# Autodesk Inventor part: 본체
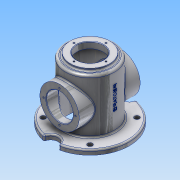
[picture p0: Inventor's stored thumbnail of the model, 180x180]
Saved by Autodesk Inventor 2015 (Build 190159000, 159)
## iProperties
Created: 2018-04
Part Number: 본체
Material: 알루미늄 6061
Document SubType Name: Modeling
Designer: SCD-A04
Density: 2.7 g/cm^3
Appearance: 알루미늄 - 평지
Mass: 1147.05 g
Surface Area: 1200.36 cm^2
Volume: 424.833 cm^3
Author: SCD-A04
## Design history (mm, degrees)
sketch "스케치1"
  geometry: C1 r 80 at (0, 0); 1 further point
  constraints: 1 centre point, 1 coincident
  dimensions: "d0" = 160 diameter of C1
extrude "돌출1" new body sketch "스케치1" distance "d1" = 10; taper "d2" = 0 deg
sketch "스케치2"
  geometry: C1 r 80 at (0, 0) reference; C2 r 50 at (0, 0)
  constraints: 1 centre point, 1 coincident
  dimensions: "d3" = 100 diameter of C2
extrude "돌출2" join sketch "스케치2" distance "d4" = 8; taper "d5" = 0 deg
sketch "스케치3"
  geometry: C1 r 80 at (0, 0) reference; C2 r 50 at (0, 0)
  constraints: 1 centre point, 1 coincident
  dimensions: "d6" = 100 diameter of C2
extrude "돌출3" join sketch "스케치3" distance "d7" = 110; taper "d8" = 0 deg
sketch "스케치4"
  geometry: C1 r 50 at (0, 0) reference; C2 r 40 at (0, 0)
  constraints: 1 centre point, 1 coincident
  dimensions: "d9" = 80 diameter of C2
extrude "돌출4" join sketch "스케치4" distance "d10" = 5; taper "d11" = 0 deg
node "작업 평면1"
sketch "스케치5"
  geometry: L1 (-80, 0)-(80, 0) reference; C1 r 40 at (0, 60); 1 further point
  constraints: 1 centre point, 1 vertical alignment
  dimensions: "d13" = 80 diameter of C1; "d14" = 60 distance from line of L1 C1.centre
extrude "돌출5" join sketch "스케치5" distance "d15" = 124; taper "d16" = 0 deg
hole "구멍1" diameter "d19" = 90; stored, may be unused: countersink angle "d23" = 90 deg, drill point angle "d25" = 0 deg; dims "d17" = 10, "d18" = 10, "d20" = 6, "d21" = 4, "d22" = 2, "d24" = 120
hole "구멍2" diameter "d28" = 54; stored, may be unused: countersink angle "d32" = 90 deg, drill point angle "d34" = 0 deg; dims "d26" = 10, "d27" = 10, "d29" = 6, "d30" = 4, "d31" = 2, "d33" = 120
hole "구멍3" diameter "d37" = 54; stored, may be unused: countersink angle "d41" = 90 deg, drill point angle "d43" = 0 deg; dims "d35" = 10, "d36" = 10, "d38" = 6, "d39" = 4, "d40" = 2, "d42" = 120
sketch "스케치6"
  geometry: C1 r 15 at (0, -80); 1 further point
  constraints: 1 centre point, 1 vertical alignment, 1 other
  dimensions: "d44" = 30 diameter of C1
extrude "돌출6" cut sketch "스케치6" stored distance "d45" = 124; taper "d46" = 0 deg
sketch "스케치7"
  geometry: C1 r 27 at (0, 0) reference; 2 further points
  dimensions: "d47" = 32.5 distance of C1.centre point (0, 32.5)
hole "구멍4" sketch "스케치7" at (0, 32.5) diameter "d48" = 3.242; stored, may be unused: countersink angle "d52" = 90 deg, drill point angle "d54" = 118 deg; dims "d49" = 8, "d50" = 4, "d51" = 2, "d53" = 10
sketch "스케치8"
  geometry: C1 r 27 at (0, 0) reference; 1 further point
  dimensions: "d58" = 32.5 distance of C1.centre point (-32.5, 0)
hole "구멍5" sketch "스케치8" at (-32.5, 0) diameter "d59" = 3.242; stored, may be unused: countersink angle "d63" = 90 deg, drill point angle "d65" = 118 deg; dims "d60" = 8, "d61" = 4, "d62" = 2, "d64" = 10
fillet "모깎기1" dims "d69" = 5
fillet "모깎기2" dims "d70" = 3
fillet "모깎기3" dims "d71" = 3
fillet "모깎기4" dims "d72" = 3
fillet "모깎기5" dims "d73" = 3
chamfer "모따기1" distance "d74" = 1; stored, may be unused: second distance "d75" = 2, angle "d76" = 45 deg
fillet "모깎기6" dims "d77" = 3
sketch "스케치9" dims "d80" = 135
  geometry: L1 (0, 0)-(47.73, -47.73); L2 (0, 0)-(39.455, 0); C1 r 5 at (47.73, -47.73); A1 r 77 centre (0, 0) between (17.301, -75.031) and (17.301, 75.031) reference; 1 further point
  constraints: 4 end point, 2 coincident, 1 centre point, 1 horizontal, 3 other
  dimensions: "d78" = 45 deg angle of L2 L1; "d81" = 10 diameter of C1
extrude "돌출7" cut sketch "스케치9" distance "d82" = 124; taper "d83" = 0 deg
node "작업 평면2"
sketch "스케치10"
  geometry: L1 (-77.955, 0)-(77.955, 0) reference; 2 further points
  constraints: 1 other
  dimensions: "d88" = 70 distance from line of point (0.578, 70) L1
feature "엠보싱1" sketch "스케치10" dims "d89" = 0.5, "d90" = 0
fillet "모깎기7" dims "d91" = 3
node "솔리드1"
mirror "대칭1"
pattern_circular "원형 패턴1" dims angle "d56" = 360 deg
mirror "대칭2"
pattern_circular "원형 패턴2" dims angle "d67" = 360 deg
pattern_circular "원형 패턴3" dims angle "d85" = 360 deg
other parameters: "d12" = -62, "d87" = 97.75
